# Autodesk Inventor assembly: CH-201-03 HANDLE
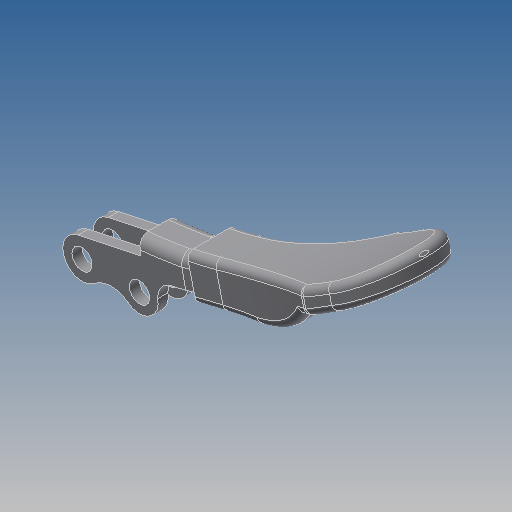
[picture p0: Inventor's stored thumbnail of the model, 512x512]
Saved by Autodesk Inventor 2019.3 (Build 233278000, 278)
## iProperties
Created: 2012-09
Part Number: CH-201-03 HANDLE
Material: Ogólny
Document SubType Name: Assembly
Designer: CADENGINEERING4
Author: CADENGINEERING4
Revision Number: ÈÎºÎ
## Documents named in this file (3)
- E:\STRONA\Horizontal toggle clamp\CH-201\CH-201-03 HANDLE.iam
- E:\STRONA\Horizontal toggle clamp\CH-201\CH-201-A-03.ipt
- E:\STRONA\Horizontal toggle clamp\CH-201\CH-201-A-05.ipt
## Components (2 placed, 2 different names)
1. CH-201-A-03_15
2. CH-201-A-05_16
